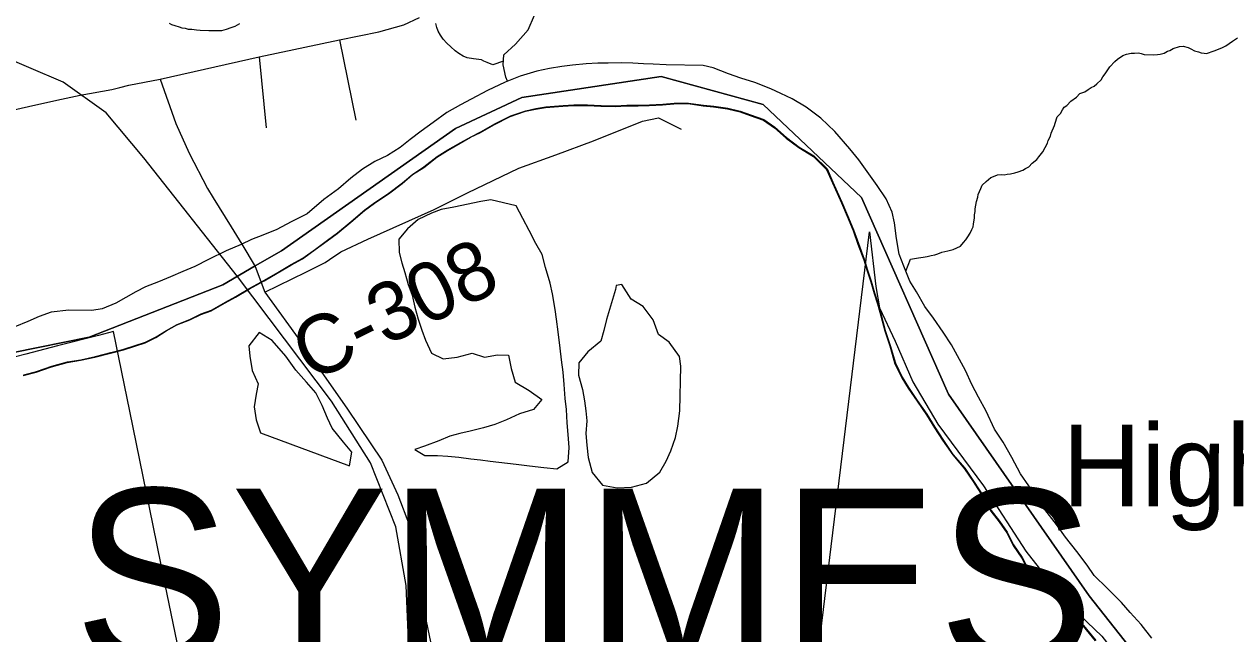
# Model space of a CAD drawing. Extents: x 44.2 to 78.2, y 4.5 to 26.5.
# Drawn here: x 49.189 to 50.361, y 24.054 to 24.644 of the extents above; entities that cross this region are included whole.
import ezdxf

# ---------------------------------------------------------------- set-up
doc = ezdxf.new("R2010")
doc.units = 0
for name, color, linetype in [('GM_X_County_Road', 7, 'Continuous'), ('GM_X_County_Road_Text', 7, 'Continuous'), ('GM_X_Interstate_Route', 7, 'Continuous'), ('GM_X_Major_River', 7, 'Continuous'), ('GM_X_Minor_Lake', 7, 'Continuous'), ('GM_X_Minor_River', 7, 'Continuous'), ('GM_X_Rail_Line', 7, 'Continuous'), ('GM_X_Section', 7, 'Continuous'), ('GM_X_State_Route', 7, 'Continuous'), ('GM_X_Township_Road', 7, 'Continuous'), ('GM_X_Township_Text', 7, 'Continuous'), ('GM_X_Unincorporated_Text', 7, 'Continuous'), ('SH_Cut_Line', 7, 'Continuous')]:
    doc.layers.add(name, color=color, linetype=linetype)

msp = doc.modelspace()

# ---------------------------------------------------------------- linework, layer by layer
at = {"layer": 'GM_X_County_Road'}
for points in [[(49.3202, 24.5908), (49.4157, 24.6125), (49.4934, 24.6288), (49.5317, 24.6368), (49.5557, 24.6434), (49.5708, 24.6505)], [(49.7027, 24.5178), (49.7393, 24.5312), (49.7866, 24.5502), (49.8023, 24.5536), (49.824, 24.5425)], [(49.4839, 24.4163), (49.4949, 24.4237), (49.5209, 24.436), (49.5852, 24.4648), (49.6175, 24.4809), (49.6669, 24.5048), (49.7027, 24.5178)], [(49.4212, 24.3847), (49.4609, 24.4041), (49.4796, 24.4134), (49.4839, 24.4163)]]:
    msp.add_lwpolyline(points, dxfattribs=at)
at = {"layer": 'GM_X_Interstate_Route'}
msp.add_lwpolyline([(49.3366, 24.0458), (49.3248, 24.102), (49.3134, 24.159), (49.2972, 24.2379), (49.2906, 24.2697), (49.2751, 24.3467), (49.2603, 24.3429), (49.2209, 24.3328), (49.19, 24.3249), (49.1398, 24.312)], dxfattribs=at)
at = {"layer": 'GM_X_Major_River'}
for points in [[(49.9958, 24.5128), (49.9873, 24.5236), (49.9728, 24.5403), (49.9591, 24.5531), (49.9449, 24.5637), (49.9314, 24.572), (49.9205, 24.5771), (49.9107, 24.5815), (49.8953, 24.5875), (49.8817, 24.592), (49.87, 24.596), (49.855, 24.6017), (49.8452, 24.6042), (49.8095, 24.6049), (49.797, 24.6055), (49.7875, 24.6057), (49.7773, 24.6063), (49.7663, 24.6066), (49.7534, 24.6064), (49.7435, 24.6063), (49.7321, 24.6057), (49.7188, 24.6045), (49.7085, 24.6032), (49.6967, 24.6011), (49.6845, 24.5987), (49.6684, 24.5937), (49.6539, 24.588), (49.6366, 24.5799), (49.6209, 24.5715), (49.6105, 24.566), (49.5974, 24.5587), (49.5843, 24.5491), (49.5724, 24.5406), (49.5619, 24.5324), (49.5523, 24.5246), (49.5399, 24.5169), (49.5277, 24.5111), (49.5157, 24.5037), (49.5045, 24.4952), (49.4926, 24.4848), (49.4783, 24.4744), (49.4624, 24.4607), (49.4467, 24.4527), (49.4329, 24.4453), (49.4194, 24.4399), (49.4083, 24.4356), (49.3984, 24.4308), (49.3838, 24.4247), (49.3669, 24.4163), (49.3535, 24.4097), (49.342, 24.4046), (49.3301, 24.3995), (49.3186, 24.3948), (49.306, 24.3898), (49.2964, 24.385), (49.2772, 24.374), (49.2641, 24.3686), (49.2539, 24.3669), (49.2318, 24.3673), (49.2147, 24.3654), (49.2029, 24.3611), (49.1921, 24.3564), (49.1795, 24.3513)], [(49.1876, 24.304), (49.2002, 24.3075), (49.2151, 24.3126), (49.23, 24.3168), (49.2429, 24.3188), (49.257, 24.322), (49.2719, 24.3258), (49.2845, 24.329), (49.2956, 24.3326), (49.3056, 24.3358), (49.3159, 24.3409), (49.3259, 24.3472), (49.3363, 24.353), (49.3489, 24.3581), (49.3593, 24.3632), (49.3693, 24.3668), (49.3831, 24.3745), (49.3931, 24.38), (49.4065, 24.3881), (49.4208, 24.3958), (49.4334, 24.4031), (49.4465, 24.4108), (49.4577, 24.4171), (49.47, 24.4259), (49.4816, 24.4344), (49.4912, 24.4415), (49.5044, 24.4526), (49.5179, 24.4637), (49.5275, 24.4708), (49.541, 24.48), (49.5542, 24.49), (49.5642, 24.4985), (49.575, 24.5055), (49.5877, 24.5155), (49.5981, 24.5218), (49.6104, 24.5291), (49.6204, 24.5346), (49.63, 24.5394), (49.6435, 24.5471), (49.6588, 24.5548), (49.6734, 24.5598), (49.6833, 24.5619), (49.6928, 24.5636), (49.7095, 24.5647), (49.7198, 24.5653), (49.7331, 24.5654), (49.7464, 24.5647), (49.7604, 24.5645), (49.771, 24.565), (49.7824, 24.5651), (49.7931, 24.5653), (49.806, 24.5662), (49.817, 24.5671), (49.8307, 24.5672), (49.8454, 24.565), (49.8553, 24.564)], [(49.1879, 24.3046), (49.2005, 24.3081), (49.2154, 24.3131), (49.2303, 24.3174), (49.2433, 24.3194), (49.2574, 24.3225), (49.2723, 24.3264), (49.2849, 24.3296), (49.296, 24.3332), (49.3059, 24.3364), (49.3163, 24.3415), (49.3263, 24.3477), (49.3366, 24.3536), (49.3493, 24.3587), (49.3596, 24.3638), (49.3696, 24.3674), (49.3834, 24.3751), (49.3934, 24.3806), (49.4069, 24.3887), (49.4211, 24.3964), (49.4338, 24.4037), (49.4469, 24.4114), (49.458, 24.4177), (49.4703, 24.4265), (49.4819, 24.435), (49.4916, 24.4421), (49.5047, 24.4532), (49.5182, 24.4643), (49.5279, 24.4714), (49.5414, 24.4806), (49.5545, 24.4906), (49.5646, 24.4991), (49.5753, 24.5061), (49.5881, 24.5161), (49.5985, 24.5224), (49.6108, 24.5297), (49.6208, 24.5352), (49.6304, 24.54), (49.6438, 24.5477), (49.6592, 24.5553), (49.6737, 24.5604), (49.6836, 24.5624), (49.6931, 24.5642), (49.7099, 24.5653), (49.7201, 24.5659), (49.7334, 24.566), (49.7467, 24.5653), (49.7607, 24.565), (49.7714, 24.5656), (49.7828, 24.5657), (49.7934, 24.5659), (49.8063, 24.5668), (49.8174, 24.5677), (49.831, 24.5678), (49.8458, 24.5656), (49.8556, 24.5646)], [(49.8556, 24.5646), (49.8693, 24.5628), (49.8813, 24.5599), (49.8911, 24.5563), (49.9039, 24.5518), (49.9148, 24.5444), (49.926, 24.5343), (49.9383, 24.5252), (49.9525, 24.5166), (49.9652, 24.5042), (49.9709, 24.4911), (49.9796, 24.4719), (49.985, 24.4589), (49.9908, 24.4451), (49.9955, 24.4317), (50.0012, 24.4167), (50.0044, 24.406), (50.0079, 24.3953), (50.0111, 24.3842), (50.0143, 24.3742), (50.0175, 24.3624), (50.0213, 24.3478), (50.0263, 24.3333), (50.0313, 24.3161), (50.0378, 24.3026), (50.044, 24.2926), (50.0525, 24.2799), (50.0617, 24.2668), (50.0694, 24.2541), (50.0771, 24.2421), (50.087, 24.2278), (50.0985, 24.2143), (50.107, 24.2019), (50.1165, 24.1869), (50.1238, 24.1735), (50.1319, 24.163), (50.1393, 24.1526), (50.1455, 24.1403), (50.1539, 24.128), (50.1601, 24.1164), (50.1705, 24.1033), (50.1802, 24.0943), (50.1939, 24.0823), (50.2051, 24.0718), (50.2162, 24.0586), (50.2251, 24.0478)], [(49.8553, 24.564), (49.8689, 24.5622), (49.881, 24.5593), (49.8908, 24.5557), (49.9036, 24.5512), (49.9145, 24.5438), (49.9256, 24.5337), (49.938, 24.5247), (49.9522, 24.516), (49.9648, 24.5036), (49.9706, 24.4905), (49.9793, 24.4713), (49.9847, 24.4583), (49.9905, 24.4445), (49.9951, 24.4311), (50.0009, 24.4161), (50.004, 24.4054), (50.0076, 24.3947), (50.0108, 24.3836), (50.014, 24.3736), (50.0171, 24.3618), (50.021, 24.3473), (50.026, 24.3327), (50.0309, 24.3155), (50.0375, 24.302), (50.0437, 24.292), (50.0522, 24.2793), (50.0614, 24.2662), (50.0691, 24.2535), (50.0768, 24.2415), (50.0867, 24.2273), (50.0982, 24.2137), (50.1066, 24.2014), (50.1162, 24.1863), (50.1235, 24.1729), (50.1316, 24.1624), (50.139, 24.152), (50.1451, 24.1397), (50.1536, 24.1274), (50.1598, 24.1158), (50.1702, 24.1027), (50.1798, 24.0938), (50.1936, 24.0817), (50.2048, 24.0712), (50.2159, 24.058), (50.2247, 24.0472)], [(50.2795, 24.0499), (50.2691, 24.063), (50.2584, 24.0746), (50.2499, 24.0843), (50.2361, 24.0983), (50.2235, 24.1107), (50.2169, 24.1207), (50.2069, 24.1339), (50.1958, 24.1478), (50.187, 24.1598), (50.1759, 24.1745), (50.1678, 24.1849), (50.1605, 24.1972), (50.1524, 24.2088), (50.144, 24.2249), (50.1356, 24.2396), (50.1271, 24.2523), (50.1191, 24.2696), (50.1118, 24.283), (50.1053, 24.2953), (50.0991, 24.3088), (50.0933, 24.3195), (50.0856, 24.3338), (50.0775, 24.3461), (50.068, 24.3596), (50.0599, 24.3708), (50.0518, 24.385), (50.0452, 24.3954), (50.0395, 24.41), (50.0351, 24.4215), (50.0324, 24.4368), (50.0305, 24.452), (50.0281, 24.4623), (50.0223, 24.475), (50.0138, 24.4881), (50.0057, 24.4993), (49.9958, 24.5128)]]:
    msp.add_lwpolyline(points, dxfattribs=at)
at = {"layer": 'GM_X_Minor_Lake'}
for points in [[(49.6401, 24.4742), (49.6302, 24.4725), (49.6042, 24.4669), (49.592, 24.4649), (49.5824, 24.4613), (49.5698, 24.4551), (49.5593, 24.4462), (49.5511, 24.4361), (49.5513, 24.4232), (49.5537, 24.4133), (49.5569, 24.4037), (49.5601, 24.3922), (49.5637, 24.3819), (49.5665, 24.3701), (49.5697, 24.3586), (49.5733, 24.3479), (49.5769, 24.3383), (49.5827, 24.3257), (49.594, 24.3201), (49.6073, 24.3217), (49.6218, 24.3256), (49.6339, 24.3219), (49.6465, 24.324), (49.6571, 24.3237), (49.6595, 24.3108), (49.6634, 24.2978), (49.6769, 24.2895), (49.6893, 24.2809), (49.6811, 24.2712), (49.6677, 24.2669), (49.6551, 24.2611), (49.6439, 24.2568), (49.6329, 24.2536), (49.6199, 24.2504), (49.61, 24.248), (49.6004, 24.2455), (49.5897, 24.2408), (49.5759, 24.2358), (49.5663, 24.2325), (49.5761, 24.2266), (49.5882, 24.2268), (49.5985, 24.2262), (49.6091, 24.2252), (49.6205, 24.2234), (49.6299, 24.2225), (49.6394, 24.2212), (49.6644, 24.2184), (49.6773, 24.2166), (49.6913, 24.2151), (49.7039, 24.2137), (49.7146, 24.2207), (49.7157, 24.2344), (49.7148, 24.2469), (49.7139, 24.2584), (49.713, 24.2713), (49.7117, 24.282), (49.7109, 24.2953), (49.71, 24.3075), (49.7083, 24.3193), (49.707, 24.3307), (49.7051, 24.3463), (49.7034, 24.3585), (49.7021, 24.368), (49.6997, 24.3833), (49.6973, 24.3936), (49.6927, 24.4085), (49.6895, 24.4211), (49.6836, 24.4319), (49.6771, 24.4445), (49.6709, 24.4561), (49.6643, 24.4684)], [(49.6643, 24.4684), (49.6401, 24.4742)], [(49.7517, 24.3583), (49.7492, 24.3477), (49.7463, 24.3375), (49.7339, 24.3271), (49.725, 24.3163), (49.7247, 24.3045), (49.7286, 24.2907), (49.7307, 24.2797), (49.732, 24.2698), (49.7329, 24.2603), (49.7319, 24.2481), (49.7328, 24.2367), (49.7341, 24.2249), (49.738, 24.2104), (49.748, 24.198), (49.762, 24.1954), (49.7761, 24.1959), (49.7906, 24.1998), (49.8033, 24.2105), (49.8096, 24.2211), (49.814, 24.2312), (49.8185, 24.2441), (49.821, 24.255), (49.8228, 24.2698), (49.8237, 24.3131), (49.8224, 24.3226), (49.8124, 24.3365), (49.8023, 24.3439), (49.7969, 24.3581), (49.7873, 24.3708), (49.7756, 24.3779), (49.7668, 24.3922)], [(49.7668, 24.3922), (49.7611, 24.3911), (49.7607, 24.3873)], [(49.7607, 24.3873), (49.7517, 24.3583)], [(49.5033, 24.2167), (49.5055, 24.23), (49.4973, 24.2397), (49.4866, 24.2532), (49.4818, 24.2628), (49.4768, 24.275), (49.4706, 24.2873), (49.4617, 24.2978), (49.4513, 24.3094), (49.4417, 24.3229), (49.4283, 24.338), (49.4159, 24.3458), (49.4058, 24.3327), (49.4067, 24.3228), (49.4091, 24.3091), (49.4149, 24.2961), (49.4128, 24.2859), (49.411, 24.2737), (49.413, 24.2612), (49.4173, 24.2485)], [(49.4173, 24.2485), (49.5033, 24.2167)]]:
    msp.add_lwpolyline(points, dxfattribs=at)
at = {"layer": 'GM_X_Minor_River'}
for points in [[(49.6562, 24.5889), (49.6544, 24.5928), (49.652, 24.6046), (49.6525, 24.6145), (49.6638, 24.6249), (49.6762, 24.6387), (49.6822, 24.6527)], [(49.3967, 24.6445), (49.3924, 24.642), (49.3886, 24.6406), (49.384, 24.6388), (49.3794, 24.6378), (49.3748, 24.6375), (49.371, 24.6376), (49.3672, 24.6377), (49.3589, 24.6379), (49.3551, 24.6384), (49.3506, 24.6389), (49.3475, 24.639), (49.3445, 24.6398), (49.3415, 24.6403), (49.3388, 24.6411), (49.3347, 24.6424), (49.3313, 24.6436), (49.3291, 24.6448)], [(49.6522, 24.6082), (49.6418, 24.6047), (49.6365, 24.6071), (49.6331, 24.6084), (49.6309, 24.6096), (49.6233, 24.6105), (49.6172, 24.6114), (49.6131, 24.6131), (49.609, 24.6158), (49.6056, 24.6182), (49.6012, 24.6221), (49.5975, 24.6256), (49.5938, 24.6295), (49.5912, 24.6334), (49.589, 24.6372), (49.5876, 24.641), (49.5866, 24.6449)], [(50.0414, 24.4051), (50.046, 24.4166), (50.0537, 24.4179), (50.0582, 24.4186), (50.0621, 24.4192), (50.0659, 24.4202), (50.0693, 24.4209), (50.0724, 24.422), (50.0762, 24.4234), (50.082, 24.4248), (50.0873, 24.4261), (50.0942, 24.4294), (50.0973, 24.4327), (50.0993, 24.4353), (50.1013, 24.4383), (50.1037, 24.442), (50.1053, 24.4454), (50.1065, 24.448), (50.1069, 24.4507), (50.1078, 24.4567), (50.1079, 24.4597), (50.1084, 24.4628), (50.1084, 24.4654), (50.1098, 24.4726), (50.111, 24.4767), (50.1114, 24.4794), (50.1139, 24.485), (50.1151, 24.4884), (50.119, 24.4917), (50.1236, 24.4957), (50.1263, 24.4968), (50.1302, 24.4982), (50.1343, 24.4985), (50.1366, 24.4984), (50.1393, 24.4991), (50.1427, 24.4994), (50.1469, 24.5004), (50.15, 24.5011), (50.1546, 24.5029), (50.1573, 24.5043), (50.1604, 24.5062), (50.1635, 24.5095), (50.1681, 24.5132), (50.1701, 24.5158), (50.174, 24.5206), (50.1784, 24.5288), (50.1792, 24.5315), (50.1812, 24.5356), (50.1821, 24.5386), (50.1853, 24.5461), (50.1857, 24.5484), (50.1878, 24.5544), (50.1909, 24.5577), (50.1929, 24.5611), (50.1945, 24.5637), (50.1972, 24.5655), (50.2011, 24.5696), (50.2065, 24.5736), (50.2096, 24.5769), (50.2146, 24.5787), (50.2177, 24.5809), (50.2208, 24.5827), (50.2235, 24.5842), (50.2262, 24.5864), (50.2305, 24.5901), (50.2321, 24.5931), (50.2341, 24.596), (50.2368, 24.5998), (50.2388, 24.6027), (50.2435, 24.6079), (50.2462, 24.6101), (50.2512, 24.6138), (50.2547, 24.6152), (50.2593, 24.6162), (50.2627, 24.6161), (50.2665, 24.6164), (50.2691, 24.6156), (50.2721, 24.6148), (50.2812, 24.6145), (50.285, 24.6148), (50.2873, 24.6151), (50.2912, 24.6162), (50.2946, 24.618), (50.2969, 24.6187), (50.3, 24.6205), (50.3061, 24.6226), (50.3096, 24.6229), (50.3145, 24.6216), (50.3171, 24.6204), (50.3205, 24.6184), (50.3246, 24.6172), (50.3272, 24.6164), (50.3299, 24.6159), (50.3322, 24.6158), (50.3398, 24.6183), (50.3471, 24.6211), (50.351, 24.6233), (50.3575, 24.6277)], [(50.3575, 24.6277), (50.3622, 24.631)]]:
    msp.add_lwpolyline(points, dxfattribs=at)
at = {"layer": 'GM_X_Rail_Line'}
for points in [[(49.3949, 24.3999), (49.3043, 24.5149), (49.2677, 24.5582), (49.2261, 24.5879), (49.1595, 24.6164), (49.1003, 24.63), (49.0093, 24.6438), (48.6841, 24.6943), (48.6131, 24.7115), (48.5641, 24.7325), (48.5189, 24.7644), (48.4811, 24.798), (48.4497, 24.8379), (48.423, 24.8802), (48.3957, 24.9436), (48.3854, 24.9898), (48.3795, 25.0434), (48.3833, 25.0995), (48.3958, 25.1552), (48.4146, 25.2129), (48.4773, 25.4014)], [(49.1046, 24.3116), (49.2515, 24.3412), (49.3807, 24.3917), (49.4119, 24.4102), (49.4376, 24.4247), (49.6058, 24.5433), (49.6698, 24.573), (49.8047, 24.5934), (49.9035, 24.5664), (49.9986, 24.4763), (50.0826, 24.2859), (50.2187, 24.0909), (50.2948, 23.9944), (50.3252, 23.8967), (50.3138, 23.7059), (50.2701, 23.6086), (50.2473, 23.5132), (50.2134, 23.4182), (50.1138, 23.3419), (50.0184, 23.2552), (49.9104, 23.0622)], [(49.9104, 23.0622), (50.0184, 23.2552), (50.1138, 23.3419), (50.2134, 23.4182), (50.2473, 23.5132), (50.2701, 23.6086), (50.3138, 23.7059), (50.3252, 23.8967), (50.2948, 23.9944), (50.2187, 24.0909), (50.0826, 24.2859), (49.9986, 24.4763), (49.9035, 24.5664), (49.8047, 24.5934), (49.6698, 24.573), (49.6058, 24.5433), (49.4376, 24.4247), (49.4119, 24.4102), (49.3807, 24.3917), (49.2515, 24.3412), (49.1046, 24.3116)], [(49.3823, 22.417), (49.4335, 22.9419), (49.5157, 23.6948), (49.5516, 23.9481), (49.5607, 24.0404), (49.5582, 24.101), (49.5479, 24.1577), (49.5234, 24.2196), (49.4858, 24.2792), (49.3949, 24.3999)]]:
    msp.add_lwpolyline(points, dxfattribs=at)
at = {"layer": 'GM_X_Section'}
msp.add_lwpolyline([(50.0124, 24.3902), (50.0159, 24.3697), (50.0312, 24.3372), (50.0483, 24.2979), (50.0722, 24.257), (50.1166, 24.1972), (50.1576, 24.134), (50.1952, 24.0862), (50.231, 24.052), (50.2549, 24.0213), (50.2652, 23.9871), (50.2823, 23.9496), (50.2993, 23.9137), (50.2993, 23.8932), (50.2976, 23.8574), (50.2959, 23.801), (50.2959, 23.7583), (50.2993, 23.7293), (50.2916, 23.682), (49.9184, 23.7227), (50.0064, 24.4433)], close=True, dxfattribs=at)
at = {"layer": 'GM_X_State_Route'}
for points in [[(49.281, 24.5828), (49.2897, 24.5851), (49.3202, 24.5908)], [(49.3202, 24.5908), (49.3354, 24.5479), (49.3482, 24.5192), (49.366, 24.485), (49.3715, 24.4759)], [(48.8767, 24.5086), (48.8866, 24.5097), (48.9027, 24.5118), (48.9567, 24.5181), (48.9938, 24.5242), (49.0062, 24.5253), (49.0131, 24.5265), (49.0415, 24.5304), (49.0557, 24.5337), (49.0827, 24.5394), (49.1081, 24.5451), (49.1178, 24.5474), (49.1315, 24.5508), (49.1427, 24.5534), (49.1557, 24.556), (49.1927, 24.5645), (49.2202, 24.5705), (49.2427, 24.5753), (49.2734, 24.5808), (49.281, 24.5828)], [(49.3715, 24.4759), (49.3771, 24.4668), (49.3888, 24.448), (49.3991, 24.4311), (49.4121, 24.4096)], [(49.4121, 24.4096), (49.4212, 24.3847), (49.4577, 24.3343), (49.4721, 24.3136)], [(49.4721, 24.3136), (49.4737, 24.3112), (49.5014, 24.2714), (49.5344, 24.2223), (49.5499, 24.1885), (49.5614, 24.1591), (49.5702, 24.1122), (49.572, 24.0924), (49.5816, 24.0463)]]:
    msp.add_lwpolyline(points, dxfattribs=at)
at = {"layer": 'GM_X_Township_Road'}
for p, q in [((49.4934, 24.6288), (49.5094, 24.5511)), ((49.4157, 24.6125), (49.4225, 24.5437))]:
    msp.add_line(p, q, dxfattribs=at)
at = {"layer": 'SH_Cut_Line'}
for points in [[(49.9104, 23.0622), (50.0184, 23.2552), (50.1138, 23.3419), (50.2134, 23.4182), (50.2473, 23.5132), (50.2701, 23.6086), (50.3138, 23.7059), (50.3252, 23.8967), (50.2948, 23.9944), (50.2187, 24.0909), (50.0826, 24.2859), (49.9986, 24.4763), (49.9035, 24.5664), (49.8047, 24.5934), (49.6698, 24.573), (49.6058, 24.5433), (49.4376, 24.4247), (49.4119, 24.4102), (49.3807, 24.3917), (49.2515, 24.3412), (49.1046, 24.3116)], [(49.1046, 24.3116), (49.2515, 24.3412), (49.3807, 24.3917), (49.4119, 24.4102), (49.4376, 24.4247), (49.6058, 24.5433), (49.6698, 24.573), (49.8047, 24.5934), (49.9035, 24.5664), (49.9986, 24.4763), (50.0826, 24.2859), (50.2187, 24.0909), (50.2948, 23.9944), (50.3252, 23.8967), (50.3138, 23.7059), (50.2701, 23.6086), (50.2473, 23.5132), (50.2134, 23.4182), (50.1138, 23.3419), (50.0184, 23.2552), (49.9104, 23.0622)]]:
    msp.add_lwpolyline(points, dxfattribs=at)

# ---------------------------------------------------------------- texts
at = {"layer": 'GM_X_County_Road_Text'}
msp.add_text('C-308', height=0.05682, rotation=26.1956, dxfattribs=at).set_placement((49.4662, 24.297))
at = {"layer": 'GM_X_Township_Text'}
msp.add_text('SYMMES', height=0.17045, rotation=0, dxfattribs=at).set_placement((49.2364, 24.0241))
at = {"layer": 'GM_X_Unincorporated_Text'}
msp.add_text('Highlands', height=0.07898, rotation=0, dxfattribs=at).set_placement((50.1928, 24.1774))

doc.saveas('drawing.dxf')
